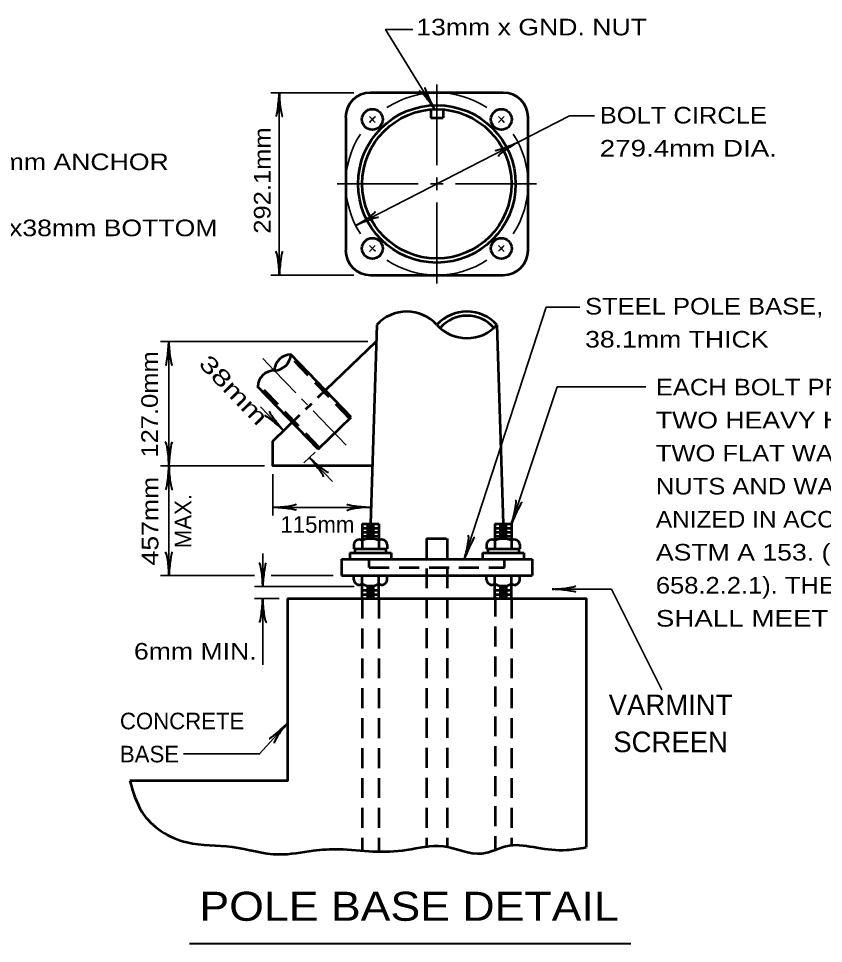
# Model space of a CAD drawing. Extents: x -29 to 827, y -14 to 530.
# Drawn here: x 340.2 to 457.6, y 191.8 to 326.7 of the extents above; entities that cross this region are included whole.
import ezdxf
from ezdxf.enums import TextEntityAlignment as Align

# ---------------------------------------------------------------- set-up
doc = ezdxf.new("R2010")
doc.units = 0
doc.header["$LTSCALE"] = 0.97
doc.linetypes.add('MEDIUM_DASHED', pattern=[4.5, 3, -1.5])
doc.layers.add('1', color=7, linetype='Continuous', lineweight=53)

msp = doc.modelspace()

# ---------------------------------------------------------------- linework, layer by layer
at = {"layer": '1', "lineweight": 35}
for p, q in [((401.2415, 317.1205), (401.2415, 305.3125)), ((389.1455, 315.8965), (377.0495, 315.8965)), ((378.2495, 315.8965), (378.2495, 289.3045)), ((420.6095, 312.5365), (389.4095, 296.5285)), ((391.4015, 312.4405), (392.2655, 311.5765)), ((411.0815, 312.4405), (410.2175, 311.5765)), ((420.6095, 312.5365), (424.2335, 312.5365)), ((386.7215, 302.6005), (398.5295, 302.6005)), ((403.9535, 302.6005), (415.7615, 302.6005)), ((401.2415, 299.8885), (401.2415, 288.0805)), ((392.2655, 293.6245), (391.4015, 292.7605)), ((410.2175, 293.6245), (411.0815, 292.7605)), ((389.1455, 289.3045), (377.0495, 289.3045)), ((391.1855, 279.6325), (360.9455, 279.6325)), ((362.1695, 279.6325), (362.1695, 261.4645)), ((382.3535, 270.3685), (381.5135, 271.2565)), ((378.8735, 266.6005), (375.5375, 270.1045)), ((388.0175, 264.4885), (383.1935, 269.5045)), ((381.8255, 261.8965), (383.4815, 263.4805)), ((386.0255, 259.2085), (382.6655, 262.6885)), ((376.1135, 261.4645), (360.9455, 261.4645)), ((362.1695, 261.4645), (362.1695, 245.4565)), ((377.3135, 260.2645), (377.3135, 254.2165)), ((377.3135, 255.4165), (391.5935, 255.4165)), ((375.8495, 243.8485), (375.8495, 248.6725)), ((374.6495, 245.4565), (360.9455, 245.4565)), ((386.1215, 245.4565), (377.0735, 245.4565)), ((389.1695, 243.8485), (374.6495, 243.8485)), ((378.2495, 242.1205), (374.6495, 242.1205)), ((375.8495, 242.1205), (375.8495, 232.4485))]:
    msp.add_line(p, q, dxfattribs=at)
at = {"layer": '1'}
for p, q in [((410.9135, 315.8965), (391.5695, 315.8965)), ((400.3415, 313.451), (400.3415, 312.251)), ((402.1415, 313.4514), (402.1415, 312.2514)), ((387.9455, 312.2725), (387.9455, 292.9285)), ((400.3415, 312.251), (402.1415, 312.2514)), ((414.5375, 292.9285), (414.5375, 312.2725)), ((391.5695, 289.3045), (410.9135, 289.3045)), ((392.4815, 282.0325), (391.5695, 253.0165)), ((410.0015, 282.0325), (410.9135, 253.0165)), ((383.8655, 271.4245), (392.4095, 279.6325)), ((388.7615, 268.5685), (379.9535, 277.7125)), ((383.9135, 263.9125), (375.1055, 273.0565)), ((382.1375, 269.7445), (383.0015, 270.5845)), ((377.3135, 265.0885), (381.2735, 268.9045)), ((383.9135, 263.9125), (388.7615, 268.5685)), ((390.3455, 253.0165), (392.7695, 253.0165)), ((390.3455, 253.0165), (390.3455, 250.5925)), ((390.3455, 252.3925), (392.7695, 252.3925)), ((390.9695, 252.7045), (392.1695, 252.7045)), ((392.7695, 253.0165), (392.7695, 250.5925)), ((409.7135, 253.0165), (412.1375, 253.0165)), ((409.7135, 253.0165), (409.7135, 250.5925)), ((409.7135, 252.3925), (412.1375, 252.3925)), ((410.3135, 252.7045), (411.5135, 252.7045)), ((412.1375, 253.0165), (412.1375, 250.5925)), ((390.3455, 251.7925), (392.7695, 251.7925)), ((390.3455, 251.1925), (392.7695, 251.1925)), ((390.9695, 252.1045), (392.1695, 252.1045)), ((390.9695, 251.5045), (392.1695, 251.5045)), ((409.7135, 251.7925), (412.1375, 251.7925)), ((409.7135, 251.1925), (412.1375, 251.1925)), ((410.3135, 252.1045), (411.5135, 252.1045)), ((410.3135, 251.5045), (411.5135, 251.5045)), ((389.1455, 249.9925), (389.1455, 249.3685)), ((390.3455, 250.5925), (390.3455, 249.3685)), ((390.9695, 250.8805), (392.1695, 250.8805)), ((392.7695, 250.5925), (392.7695, 249.3685)), ((393.9935, 249.9925), (393.9935, 249.3685)), ((408.4895, 249.9925), (408.4895, 249.3685)), ((409.7135, 250.5925), (409.7135, 249.3685)), ((410.3135, 250.8805), (411.5135, 250.8805)), ((412.1375, 250.5925), (412.1375, 249.3685)), ((413.3375, 249.9925), (413.3375, 249.3685)), ((388.5455, 248.7685), (394.5935, 248.7685)), ((388.5455, 248.7685), (388.5455, 247.8565)), ((389.1455, 249.3685), (393.9935, 249.3685)), ((389.2895, 249.3685), (389.2895, 248.7685)), ((393.8255, 249.3685), (393.8255, 248.7685)), ((394.5935, 248.7685), (394.5935, 247.8565)), ((407.8895, 248.7685), (413.9375, 248.7685)), ((407.8895, 248.7685), (407.8895, 247.8565)), ((408.4895, 249.3685), (413.3375, 249.3685)), ((408.6575, 249.3685), (408.6575, 248.7685)), ((413.1935, 249.3685), (413.1935, 248.7685)), ((413.9375, 248.7685), (413.9375, 247.8565)), ((387.3215, 247.8565), (415.1615, 247.8565)), ((387.3215, 247.8565), (387.3215, 245.4565)), ((415.1615, 247.8565), (415.1615, 245.4565)), ((387.3215, 245.4565), (415.1615, 245.4565)), ((389.1455, 244.8325), (389.1455, 245.4565)), ((390.3455, 242.1205), (390.3455, 245.4565)), ((392.7695, 242.1205), (392.7695, 245.4565)), ((393.9935, 244.8325), (393.9935, 245.4565)), ((408.4895, 244.8325), (408.4895, 245.4565)), ((409.7135, 242.1205), (409.7135, 245.4565)), ((412.1375, 242.1205), (412.1375, 245.4565)), ((413.3375, 244.8325), (413.3375, 245.4565)), ((390.3455, 243.3205), (392.7695, 243.3205)), ((390.9695, 243.6325), (392.1695, 243.6325)), ((390.9695, 243.0325), (392.1695, 243.0325)), ((409.7135, 243.3205), (412.1375, 243.3205)), ((410.3375, 243.6325), (411.5375, 243.6325)), ((410.3375, 243.0325), (411.5375, 243.0325)), ((390.3455, 242.7205), (392.7695, 242.7205)), ((390.3455, 242.1205), (392.7695, 242.1205)), ((390.9695, 242.4325), (392.1695, 242.4325)), ((409.7135, 242.7205), (412.1375, 242.7205)), ((409.7135, 242.1205), (412.1375, 242.1205)), ((410.3375, 242.4325), (411.5375, 242.4325))]:
    msp.add_line(p, q, dxfattribs=at)
at = {"layer": '1', "linetype": 'MEDIUM_DASHED'}
for p, q in [((388.5455, 268.3525), (379.9055, 277.3285)), ((384.1295, 264.1045), (375.1775, 273.4405)), ((399.7295, 250.8805), (399.7295, 205.7605)), ((399.7295, 250.8805), (402.7535, 250.8805)), ((402.7535, 250.8805), (402.7535, 206.0005)), ((391.3775, 246.6565), (391.3775, 247.8565)), ((411.1295, 246.6565), (411.1295, 247.8565)), ((391.3775, 246.6565), (411.1295, 246.6565)), ((390.3455, 242.1205), (390.3455, 205.3045)), ((392.7695, 242.1205), (392.7695, 205.2565)), ((409.7375, 242.3845), (409.7375, 205.5205)), ((412.1375, 242.1205), (412.1375, 206.0725))]:
    msp.add_line(p, q, dxfattribs=at)
at = {"layer": '1', "lineweight": 40}
msp.add_line((365.1695, 191.7925), (429.5135, 191.7925), dxfattribs=at)
at = {"layer": '1', "lineweight": 35}
for points in [[(400.9083, 313.4833), (393.7631, 325.1473), (397.7549, 325.1473)], [(400.3295, 302.6005), (401.2415, 302.6005), (402.1535, 302.6005)], [(401.2415, 303.5125), (401.2415, 302.6005), (401.2415, 301.6885)], [(405.2495, 247.8565), (417.1775, 284.6005), (422.0975, 284.6005)], [(380.6735, 272.1205), (377.5295, 275.3845), (375.8495, 277.1365)], [(412.1375, 253.0165), (418.8095, 272.9845), (431.7401, 272.9845)], [(418.0511, 243.4901), (426.6921, 243.4901), (434.0462, 228.7771)], [(379.4735, 223.9285), (375.3935, 219.4405), (364.3055, 219.4405)]]:
    msp.add_lwpolyline(points, dxfattribs=at)
at = {"layer": '1'}
for points in [[(391.8335, 261.4645), (377.3135, 261.4645), (377.3135, 265.0885)], [(379.4735, 242.1205), (379.4735, 215.5045), (356.4815, 215.5045)], [(379.4735, 242.1205), (423.0095, 242.1205), (423.0095, 205.8325)]]:
    msp.add_lwpolyline(points, dxfattribs=at)
for centre, radius in [((401.2438, 302.6021), 11.4912), ((391.8353, 312.0106), 1.512), ((401.2438, 302.6021), 10.8864), ((410.6522, 312.0106), 1.512), ((391.8353, 293.1936), 1.512), ((410.6522, 293.1936), 1.512)]:
    msp.add_circle(centre, radius, dxfattribs=at)
for centre, radius, start, end in [((391.567, 312.2789), 3.6288, 90, 180), ((410.9206, 312.2789), 3.6288, 0, 90), ((391.567, 292.9253), 3.6288, 180, 270), ((410.9206, 292.9253), 3.6288, 270, 0), ((396.859, 278.0719), 5.913, 42.13622, 137.86423), ((405.6286, 278.0719), 5.913, 42.13622, 137.86378), ((405.6626, 278.1736), 5.2007, 41.23283, 139.26556), ((405.6286, 286.0059), 5.913, 222.13622, 317.86378), ((380.0269, 275.2235), 2.4958, 91.57437, 176.25114), ((377.4678, 277.8816), 2.4958, 271.57437, 356.25114), ((377.605, 272.8918), 2.4958, 91.57437, 176.25114), ((389.9355, 249.9211), 0.7903, 57.73362, 175.39648), ((391.567, 248.0686), 2.7959, 64.36559, 115.6344), ((393.1984, 249.9211), 0.7903, 4.60352, 122.26638), ((409.2891, 249.9211), 0.7903, 57.73362, 175.39648), ((410.9206, 248.0686), 2.7959, 64.36559, 115.6344), ((412.552, 249.9211), 0.7903, 4.60352, 122.26638), ((389.9355, 244.9071), 0.7903, 184.60352, 302.26638), ((391.567, 246.7596), 2.7959, 244.3656, 295.63441), ((393.1984, 244.9071), 0.7903, 237.73362, 355.39648), ((409.2891, 244.9071), 0.7903, 184.60352, 302.26638), ((410.9206, 246.7596), 2.7959, 244.3656, 295.63441), ((412.552, 244.9071), 0.7903, 237.73362, 355.39648)]:
    msp.add_arc(centre, radius, start, end, dxfattribs=at)
at = {"layer": '1', "lineweight": 35}
for start, end in [(56.77694, 123.15721), (132.39545, 137.60578), (42.39484, 47.60516), (146.85345, 213.14435), (326.86294, 33.16035), (222.39484, 227.60516), (312.39437, 317.6047), (236.86662, 303.17329)]:
    msp.add_arc((401.2438, 302.6021), 13.3056, start, end, dxfattribs=at)
at = {"layer": '1', "lineweight": 40}
for centre, major_axis, ratio, start_param, end_param in [((378.0054, 314.5523), (0.2125, 2.1246), 0.07063, 3.14071475, 5.41810995), ((378.0054, 314.5523), (0.2125, 2.1246), 0.07063, 3.14071475, 5.41810995), ((378.5956, 314.5878), (-0.1889, 2.16), 0.122415, 0.89635335, 3.14159265), ((378.5956, 314.5878), (-0.1889, 2.16), 0.122415, 0.89635335, 3.14159265), ((399.9416, 314.4267), (1.2791, -1.7294), 0.122415, 0.89635335, 3.14159265), ((400.4225, 314.7625), (0.9213, -1.9074), 0.07063, 3.14071475, 5.41810995), ((411.7592, 308.2855), (1.9873, 0.7809), 0.07063, 3.14071475, 5.41810995), ((411.7592, 308.2855), (1.9873, 0.7809), 0.07063, 3.14071475, 5.41810995), ((412.0601, 307.7766), (1.8355, 1.1541), 0.122415, 0.89635335, 3.14159265), ((412.0601, 307.7766), (1.8355, 1.1541), 0.122415, 0.89635335, 3.14159265), ((390.4274, 297.4276), (-1.8355, -1.1541), 0.122415, 0.89635335, 3.14159265), ((390.7283, 296.9187), (-1.9873, -0.7809), 0.07063, 3.14071475, 5.41810995), ((377.9271, 290.6164), (0.1889, -2.16), 0.122415, 0.89635335, 3.14159265), ((378.5173, 290.6519), (-0.2125, -2.1246), 0.07063, 3.14071475, 5.41810995), ((361.9026, 278.2653), (0.2125, 2.1246), 0.07063, 3.14071475, 5.41810995), ((361.9026, 278.2653), (0.2125, 2.1246), 0.07063, 3.14071475, 5.41810995), ((362.4928, 278.3007), (-0.1889, 2.16), 0.122415, 0.89635335, 3.14159265), ((362.4928, 278.3007), (-0.1889, 2.16), 0.122415, 0.89635335, 3.14159265), ((377.7279, 267.3289), (1.6342, -1.425), 0.122415, 0.89635335, 3.14159265), ((377.7279, 267.3289), (1.6342, -1.425), 0.122415, 0.89635335, 3.14159265), ((378.1284, 267.7638), (-1.3205, 1.6779), 0.07063, 6.28230741, 8.55970261), ((378.1284, 267.7638), (-1.3205, 1.6779), 0.07063, 6.28230741, 8.55970261), ((361.8243, 262.7915), (0.1889, -2.16), 0.122415, 0.89635335, 3.14159265), ((362.4145, 262.8269), (-0.2125, -2.1246), 0.07063, 3.14071475, 5.41810995), ((383.415, 261.5347), (1.3205, -1.6779), 0.07063, 6.28230741, 8.55970261), ((383.8156, 261.9696), (-1.6342, 1.425), 0.122415, 0.89635335, 3.14159265), ((361.9162, 260.1162), (0.2125, 2.1246), 0.07063, 3.14071475, 5.41810995), ((362.5064, 260.1517), (-0.1889, 2.16), 0.122415, 0.89635335, 3.14159265), ((412.2318, 254.3663), (-0.5058, -2.1084), 0.122415, 0.89635335, 3.14159265), ((412.2318, 254.3663), (-0.5058, -2.1084), 0.122415, 0.89635335, 3.14159265), ((378.6715, 255.1676), (-2.1246, 0.2125), 0.07063, 3.14071475, 5.41810995), ((378.6715, 255.1676), (-2.1246, 0.2125), 0.07063, 3.14071475, 5.41810995), ((378.6361, 255.7578), (-2.16, -0.1889), 0.122415, 0.89635335, 3.14159265), ((378.6361, 255.7578), (-2.16, -0.1889), 0.122415, 0.89635335, 3.14159265), ((390.2846, 255.0894), (2.16, 0.1889), 0.122415, 0.89635335, 3.14159265), ((390.2492, 255.6795), (2.1246, -0.2125), 0.07063, 3.14071475, 5.41810995), ((412.8027, 254.2127), (-0.8753, -1.9476), 0.07063, 3.14071475, 5.41810995), ((412.8027, 254.2127), (-0.8753, -1.9476), 0.07063, 3.14071475, 5.41810995), ((405.3393, 249.2263), (-0.4869, -2.1128), 0.122415, 0.89635335, 3.14159265), ((405.9116, 249.0779), (-0.8577, -1.9553), 0.07063, 3.14071475, 5.41810995), ((361.8379, 246.7684), (0.1889, -2.16), 0.122415, 0.89635335, 3.14159265), ((362.4281, 246.8039), (-0.2125, -2.1246), 0.07063, 3.14071475, 5.41810995), ((375.5191, 245.1592), (0.1889, -2.16), 0.122415, 0.89635335, 3.14159265), ((375.5191, 245.1592), (0.1889, -2.16), 0.122415, 0.89635335, 3.14159265), ((376.1093, 245.1947), (-0.2125, -2.1246), 0.07063, 3.14071475, 5.41810995), ((376.1093, 245.1947), (-0.2125, -2.1246), 0.07063, 3.14071475, 5.41810995), ((419.3957, 243.2362), (-2.1077, 0.2108), 0.07063, 3.14071475, 5.41810995), ((419.3605, 243.8217), (-2.1428, -0.1874), 0.122415, 0.89635335, 3.14159265), ((375.5974, 240.7667), (0.2125, 2.1246), 0.07063, 3.14071475, 5.41810995), ((376.1876, 240.8022), (-0.1889, 2.16), 0.122415, 0.89635335, 3.14159265), ((378.3688, 223.1058), (-1.5882, -1.4271), 0.07063, 6.28230741, 8.55970261), ((378.8288, 222.7344), (1.3154, 1.7236), 0.122415, 0.89635335, 3.14159265)]:
    msp.add_ellipse(centre, major_axis=major_axis, ratio=ratio, start_param=start_param, end_param=end_param, dxfattribs=at)
at = {"layer": '1'}
msp.add_spline([(356.4815, 215.5045), (358.2335, 210.9925), (364.7615, 206.5525), (371.3855, 205.8805), (378.2255, 204.8005), (383.2415, 205.3525), (386.9375, 205.5685), (391.9295, 205.2325), (396.8255, 205.4485), (402.1535, 206.0005), (407.7935, 204.9205), (411.8255, 206.0965), (415.8335, 205.7845), (420.1775, 205.4485), (423.0095, 205.8325)], degree=3, dxfattribs=at)

# ---------------------------------------------------------------- texts
for s, height, width, p in [('13mm x GND. NUT', 2.419, 1.2, (398.2434, 324.2759)), ('BOLT CIRCLE', 2.419, 1.15, (425.0015, 311.4133)), ('279.4mm DIA.', 2.419, 1.25, (425.0015, 306.5941)), ('31.75mmx1065mm ANCHOR', 2.419, 1.2, (311.0187, 304.6126)), ('125mmx125mmx38mm BOTTOM', 2.419, 1.2, (311.0187, 294.9742)), ('STEEL POLE BASE,', 2.419, 1.15, (422.8655, 283.5493)), ('38.1mm THICK', 2.419, 1.2, (422.8655, 278.7301)), ('EACH BOLT PROVIDED WITH', 2.419, 1.15, (433.1873, 271.754)), ('TWO HEAVY HEX NUTS AND', 2.419, 1.2, (433.1873, 266.9348)), ('TWO FLAT WASHERS; BOTH', 2.419, 1.15, (433.1873, 262.1156)), ('NUTS AND WASHERS GALV-', 2.419, 1.15, (433.1873, 257.2964)), ('ANIZED IN ACCORDANCE WITH', 2.419, 1.1, (433.1873, 252.4772)), ('ASTM A 153. (SEE SUBARTICLE', 2.419, 1.2, (433.1873, 247.658)), ('658.2.2.1). THE WASHERS', 2.419, 1.15, (433.1873, 242.8388)), ('SHALL MEET ASTM F 436M.', 2.419, 1.25, (433.1873, 238.0196)), ('6mm MIN.', 2.419, 1.2, (357.0633, 233.2165)), ('POLE BASE DETAIL', 4.234, 1.15, (366.6095, 195.1045))]:
    msp.add_text(s, height=height, dxfattribs=dict(at, width=width)).set_placement(p)
for s, rotation, width, p in [('292.1mm', 90, 1.15, (376.9819, 295.3375)), ('127.0mm', 90, 1.15, (360.5557, 262.6803)), ('38mm', 313.914, 1.4, (366.3703, 276.2197))]:
    msp.add_text(s, height=2.419, rotation=rotation, dxfattribs=dict(at, width=width)).set_placement(p)
at = {"layer": '1', "width": 1.2}
msp.add_text('457mm', height=2.419, rotation=90, dxfattribs=at).set_placement((360.6273, 253.4101), align=Align.CENTER)
at = {"layer": '1'}
msp.add_text('MAX.', height=2.419, rotation=90, dxfattribs=at).set_placement((365.4465, 253.4101), align=Align.CENTER)
for s, p in [('115mm', (378.4324, 251.7109)), ('CONCRETE', (355.0175, 223.0405)), ('BASE', (355.0175, 218.2165))]:
    msp.add_text(s, height=2.419, dxfattribs=at).set_placement(p)
for s, p in [('VARMINT', (435.3333, 225.1034)), ('SCREEN', (435.3333, 219.7034))]:
    msp.add_text(s, height=3, dxfattribs=at).set_placement(p, align=Align.CENTER)

doc.saveas('drawing.dxf')
